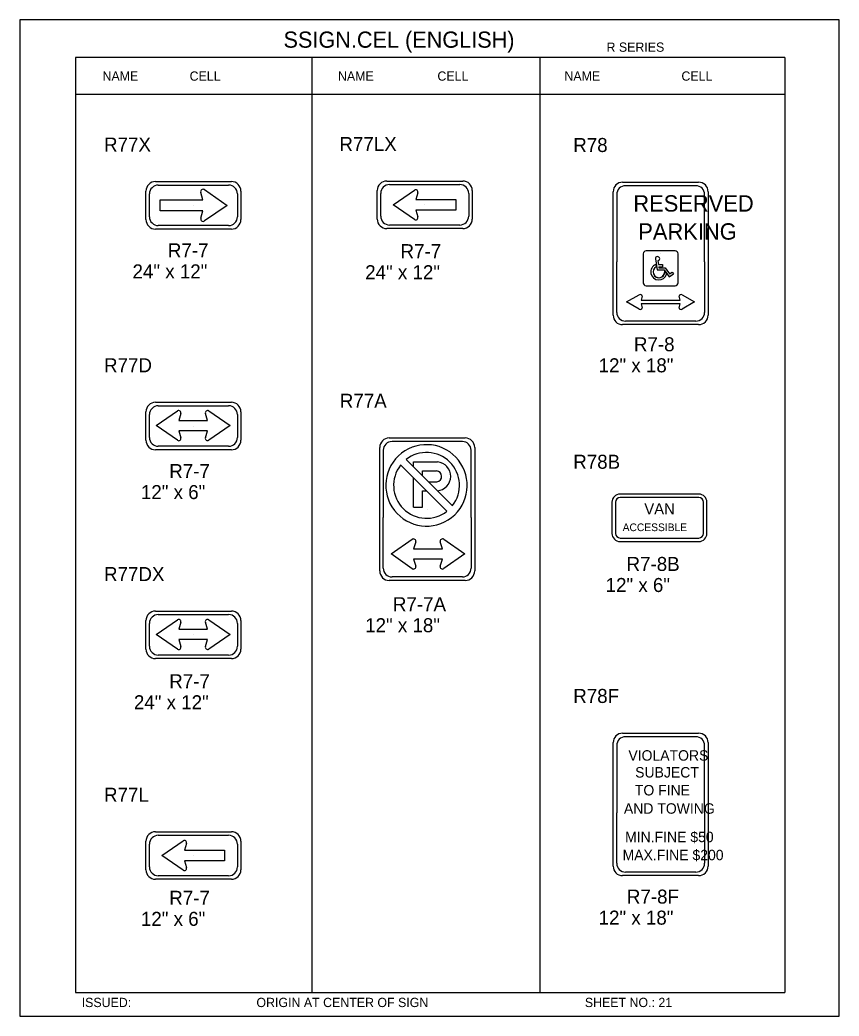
# Model space of a CAD drawing. Extents: x -5299 to 22597, y -19549 to -1808.
# Drawn here: x -3651 to -2950, y -6387 to -5535 of the extents above; entities that cross this region are included whole.
import ezdxf

# ---------------------------------------------------------------- set-up
doc = ezdxf.new("R2010")
doc.units = 0
for name, color, linetype in [('Level 1', 7, 'Continuous'), ('Level 2', 7, 'Continuous'), ('Level 3', 7, 'Continuous'), ('Level 63', 7, 'Continuous')]:
    doc.layers.add(name, color=color, linetype=linetype)

msp = doc.modelspace()

# ---------------------------------------------------------------- linework, layer by layer
at = {"layer": 'Level 1'}
for p, q in [((-2996.59, -5567.18), (-3603.6, -5567.18)), ((-3603.6, -5567.18), (-3603.6, -6367.18)), ((-3401.26, -5567.18), (-3401.26, -6367.18)), ((-3206.14, -5567.18), (-3206.14, -6367.18)), ((-2996.59, -5567.18), (-2996.59, -6367.18)), ((-2996.59, -5598.85), (-3603.6, -5598.85)), ((-3532.72, -5676.35), (-3472.51, -5676.35)), ((-3334.78, -5675.87), (-3274.58, -5675.87)), ((-3540.24, -5703.43), (-3540.24, -5683.86)), ((-3494.43, -5688.87), (-3496.34, -5682.61)), ((-3493.23, -5680.22), (-3473.83, -5693.65)), ((-3465, -5683.86), (-3465, -5703.43)), ((-3342.3, -5702.96), (-3342.3, -5683.39)), ((-3331.67, -5693.18), (-3313.48, -5680.63)), ((-3310.57, -5682.82), (-3312.36, -5688.69)), ((-3267.06, -5683.39), (-3267.06, -5702.96)), ((-3140.4, -5684.37), (-3140.4, -5741.94)), ((-3072.68, -5676.86), (-3132.88, -5676.86)), ((-3065.16, -5741.94), (-3065.16, -5684.37)), ((-3531.09, -5698.43), (-3531.09, -5688.87)), ((-3531.09, -5688.87), (-3494.43, -5688.87)), ((-3502.62, -5693.65), (-3502.62, -5693.65)), ((-3473.83, -5693.65), (-3493.23, -5707.03)), ((-3313.48, -5705.77), (-3331.67, -5693.18)), ((-3312.36, -5688.69), (-3277.99, -5688.69)), ((-3304.68, -5693.18), (-3304.68, -5693.18)), ((-3277.99, -5688.69), (-3277.99, -5697.66)), ((-3494.43, -5698.43), (-3531.09, -5698.43)), ((-3496.34, -5704.69), (-3494.43, -5698.43)), ((-3277.99, -5697.66), (-3312.36, -5697.66)), ((-3312.36, -5697.66), (-3310.57, -5703.53)), ((-3274.58, -5710.48), (-3334.78, -5710.48)), ((-3472.51, -5710.95), (-3532.72, -5710.95)), ((-3117.7, -5735.1), (-3117.7, -5759.95)), ((-3090.37, -5732.62), (-3115.22, -5732.62)), ((-3102.78, -5734.8), (-3102.78, -5734.8)), ((-3087.89, -5759.95), (-3087.89, -5735.1)), ((-3140.4, -5785.22), (-3140.4, -5741.94)), ((-3107.31, -5739.37), (-3105.86, -5748.87)), ((-3106.99, -5744.28), (-3106.69, -5746.2)), ((-3105.14, -5741.21), (-3104.67, -5744.28)), ((-3104.67, -5744.28), (-3101.05, -5744.28)), ((-3101.05, -5744.28), (-3101.05, -5746.14)), ((-3065.16, -5741.94), (-3065.16, -5785.22)), ((-3105.86, -5748.87), (-3099.77, -5748.87)), ((-3104.39, -5746.14), (-3101.05, -5746.14)), ((-3104.39, -5746.14), (-3104.26, -5747.01)), ((-3104.26, -5747.01), (-3098.81, -5747.01)), ((-3099.77, -5748.87), (-3095.55, -5754.78)), ((-3099.31, -5750.11), (-3097.66, -5752.41)), ((-3098.81, -5747.01), (-3095.08, -5752.23)), ((-3095.55, -5754.78), (-3091.81, -5752.28)), ((-3095.08, -5752.23), (-3092.85, -5750.73)), ((-3092.85, -5750.73), (-3091.81, -5752.28)), ((-3131.87, -5776.32), (-3121.28, -5770.19)), ((-3115.22, -5762.43), (-3090.37, -5762.43)), ((-3084.32, -5770.19), (-3073.72, -5776.32)), ((-3121.17, -5782.51), (-3131.87, -5776.32)), ((-3118.68, -5771.25), (-3119.5, -5774.67)), ((-3119.5, -5774.67), (-3102.8, -5774.67)), ((-3102.8, -5777.94), (-3119.44, -5777.94)), ((-3119.44, -5777.94), (-3118.61, -5781.41)), ((-3102.8, -5774.67), (-3086.09, -5774.67)), ((-3086.15, -5777.94), (-3102.8, -5777.94)), ((-3086.98, -5781.41), (-3086.15, -5777.94)), ((-3086.09, -5774.67), (-3086.91, -5771.25)), ((-3073.72, -5776.32), (-3084.42, -5782.51)), ((-3072.68, -5792.74), (-3132.88, -5792.74)), ((-3540.24, -5892.27), (-3540.24, -5872.7)), ((-3534.49, -5882.12), (-3516.3, -5869.58)), ((-3532.72, -5865.19), (-3472.51, -5865.19)), ((-3513.39, -5871.77), (-3515.18, -5877.64)), ((-3490.6, -5877.64), (-3492.39, -5871.77)), ((-3489.48, -5869.53), (-3471.29, -5882.12)), ((-3465, -5872.7), (-3465, -5892.27)), ((-3515.18, -5877.64), (-3509.16, -5877.64)), ((-3509.16, -5877.64), (-3490.6, -5877.64)), ((-3516.3, -5894.72), (-3534.49, -5882.12)), ((-3509.28, -5886.6), (-3515.18, -5886.6)), ((-3515.18, -5886.6), (-3513.39, -5892.48)), ((-3490.6, -5886.6), (-3509.28, -5886.6)), ((-3502.62, -5882.49), (-3502.62, -5882.49)), ((-3492.39, -5892.48), (-3490.6, -5886.6)), ((-3471.29, -5882.12), (-3489.48, -5894.67)), ((-3272.45, -5895.72), (-3332.66, -5895.72)), ((-3472.51, -5899.79), (-3532.72, -5899.79)), ((-3340.17, -5903.24), (-3340.17, -5960.8)), ((-3264.93, -5960.8), (-3264.93, -5903.24)), ((-3320.59, -5911.14), (-3281, -5950.73)), ((-3325.29, -5915.79), (-3285.65, -5955.43)), ((-3301.42, -5930.31), (-3294.29, -5930.31)), ((-3306.71, -5937.93), (-3303.2, -5937.93)), ((-3141.42, -5947.68), (-3141.42, -5974.32)), ((-3070.15, -5943.68), (-3137.42, -5943.68)), ((-3066.15, -5974.32), (-3066.15, -5947.68)), ((-3302.55, -5953.66), (-3302.55, -5953.66)), ((-3340.17, -6004.08), (-3340.17, -5960.8)), ((-3264.93, -5960.8), (-3264.93, -6004.08)), ((-3103.79, -5961), (-3103.79, -5961)), ((-3333.47, -5991.96), (-3315.28, -5979.41)), ((-3312.37, -5981.61), (-3314.16, -5987.48)), ((-3289.58, -5987.48), (-3291.37, -5981.61)), ((-3288.46, -5979.37), (-3270.27, -5991.96)), ((-3137.42, -5978.32), (-3070.15, -5978.32)), ((-3315.28, -6004.55), (-3333.47, -5991.96)), ((-3314.16, -5987.48), (-3308.14, -5987.48)), ((-3308.14, -5987.48), (-3289.58, -5987.48)), ((-3270.27, -5991.96), (-3288.46, -6004.51)), ((-3308.26, -5996.44), (-3314.16, -5996.44)), ((-3314.16, -5996.44), (-3312.37, -6002.31)), ((-3289.58, -5996.44), (-3308.26, -5996.44)), ((-3291.37, -6002.31), (-3289.58, -5996.44)), ((-3272.45, -6011.6), (-3332.65, -6011.6)), ((-3540.24, -6070.94), (-3540.24, -6051.38)), ((-3534.49, -6060.8), (-3516.3, -6048.25)), ((-3532.72, -6043.86), (-3472.51, -6043.86)), ((-3513.39, -6050.44), (-3515.18, -6056.31)), ((-3490.6, -6056.31), (-3492.39, -6050.44)), ((-3489.48, -6048.2), (-3471.29, -6060.8)), ((-3465, -6051.38), (-3465, -6070.94)), ((-3515.18, -6056.31), (-3509.16, -6056.31)), ((-3509.16, -6056.31), (-3490.6, -6056.31)), ((-3516.3, -6073.39), (-3534.49, -6060.8)), ((-3509.28, -6065.28), (-3515.18, -6065.28)), ((-3515.18, -6065.28), (-3513.39, -6071.15)), ((-3490.6, -6065.28), (-3509.28, -6065.28)), ((-3502.62, -6061.16), (-3502.62, -6061.16)), ((-3492.39, -6071.15), (-3490.6, -6065.28)), ((-3471.29, -6060.8), (-3489.48, -6073.34)), ((-3472.51, -6078.46), (-3532.72, -6078.46)), ((-3072.68, -6148.3), (-3132.88, -6148.3)), ((-3140.4, -6155.81), (-3140.4, -6213.37)), ((-3065.16, -6213.37), (-3065.16, -6155.81)), ((-3140.4, -6256.65), (-3140.4, -6213.37)), ((-3102.78, -6206.23), (-3102.78, -6206.23)), ((-3065.16, -6213.37), (-3065.16, -6256.65)), ((-3532.72, -6232.7), (-3472.51, -6232.7)), ((-3529.61, -6250), (-3511.41, -6237.45)), ((-3540.24, -6259.78), (-3540.24, -6240.22)), ((-3508.5, -6239.65), (-3510.29, -6245.52)), ((-3510.29, -6245.52), (-3475.93, -6245.52)), ((-3475.93, -6245.52), (-3475.93, -6254.48)), ((-3465, -6240.22), (-3465, -6259.78)), ((-3511.41, -6262.59), (-3529.61, -6250)), ((-3475.93, -6254.48), (-3510.29, -6254.48)), ((-3510.29, -6254.48), (-3508.5, -6260.35)), ((-3502.62, -6250), (-3502.62, -6250)), ((-3072.68, -6264.17), (-3132.88, -6264.17)), ((-3472.51, -6267.3), (-3532.72, -6267.3)), ((-3603.6, -6367.18), (-2996.59, -6367.18))]:
    msp.add_line(p, q, dxfattribs=at)
for points in [[(-3314.33, -5917.41), (-3314.33, -5913.09), (-3293.64, -5913.19)], [(-3306.71, -5925.02), (-3306.71, -5920.76), (-3294.51, -5920.81)], [(-3314.38, -5951.97), (-3314.33, -5926.8)], [(-3314.38, -5951.97), (-3314.38, -5952.02), (-3306.71, -5951.97), (-3306.71, -5937.93)]]:
    msp.add_lwpolyline(points, dxfattribs=at)
for centre, radius, start, end in [((-3532.72, -5683.86), 7.52, 90, 180), ((-3472.52, -5683.86), 7.52, 0, 90), ((-3334.78, -5683.39), 7.52, 90, 180), ((-3274.58, -5683.39), 7.52, 0, 90), ((-3494.33, -5682), 2.11, 58.03237, 196.37365), ((-3312.45, -5682.27), 1.96, 342.85487, 122.33442), ((-3132.88, -5684.37), 7.52, 90, 180), ((-3072.68, -5684.37), 7.52, 0, 90), ((-3532.72, -5703.43), 7.52, 180, 270), ((-3494.33, -5705.28), 2.09, 162.85487, 302.33442), ((-3472.52, -5703.43), 7.52, 270, 0), ((-3334.78, -5702.96), 7.52, 180, 270), ((-3312.45, -5704.09), 1.98, 238.03237, 16.37365), ((-3274.58, -5702.96), 7.52, 270, 0), ((-3115.22, -5735.1), 2.48, 90, 180), ((-3090.37, -5735.1), 2.48, 0, 90), ((-3104.29, -5750.6), 6.87, 113.13164, 344.68326), ((-3105.45, -5739.37), 1.86, 279.36814, 180), ((-3104.29, -5750.6), 5.01, 118.69491, 0), ((-3104.29, -5750.6), 5.01, 118.69491, 5.58069), ((-3115.22, -5759.95), 2.48, 180, 270), ((-3090.37, -5759.95), 2.48, 270, 0), ((-3132.88, -5785.22), 7.52, 180, 270), ((-3072.68, -5785.22), 7.52, 270, 0), ((-3532.72, -5872.7), 7.52, 90, 180), ((-3515.27, -5871.21), 1.96, 342.85487, 122.33442), ((-3490.51, -5871.21), 1.98, 58.03237, 196.37365), ((-3472.52, -5872.7), 7.52, 0, 90), ((-3532.72, -5892.27), 7.52, 180, 270), ((-3515.27, -5893.04), 1.98, 238.03237, 16.37365), ((-3490.51, -5893.03), 1.96, 162.85487, 302.33442), ((-3472.52, -5892.27), 7.52, 270, 0), ((-3332.66, -5903.24), 7.52, 90, 180), ((-3303.14, -5933.27), 34.84, 308.11415, 307.76212), ((-3272.45, -5903.24), 7.52, 0, 90), ((-3303.12, -5933.26), 28.18, 321.95826, 128.34318), ((-3294.88, -5925.55), 12.42, 274.98032, 84.26909), ((-3303.12, -5933.26), 28.18, 142.1255, 308.3331), ((-3294.96, -5925.58), 4.78, 278.04391, 85.86111), ((-3137.42, -5947.68), 4, 90, 180), ((-3070.15, -5947.68), 4, 0, 90), ((-3137.42, -5974.32), 4, 180, 270), ((-3070.15, -5974.32), 4, 270, 0), ((-3314.25, -5981.05), 1.96, 342.85487, 122.33442), ((-3289.49, -5981.04), 1.98, 58.03237, 196.37365), ((-3332.65, -6004.08), 7.52, 180, 270), ((-3314.25, -6002.88), 1.98, 238.03237, 16.37365), ((-3289.49, -6002.87), 1.96, 162.85487, 302.33442), ((-3272.45, -6004.08), 7.52, 270, 0), ((-3532.72, -6051.37), 7.52, 90, 180), ((-3515.27, -6049.89), 1.96, 342.85487, 122.33442), ((-3490.51, -6049.88), 1.98, 58.03237, 196.37365), ((-3472.52, -6051.37), 7.52, 0, 90), ((-3532.72, -6070.94), 7.52, 180, 270), ((-3515.27, -6071.71), 1.98, 238.03237, 16.37365), ((-3490.51, -6071.7), 1.96, 162.85487, 302.33442), ((-3472.52, -6070.94), 7.52, 270, 0), ((-3132.88, -6155.81), 7.52, 90, 180), ((-3072.68, -6155.81), 7.52, 0, 90), ((-3532.72, -6240.22), 7.52, 90, 180), ((-3510.39, -6239.09), 1.96, 342.85487, 122.33442), ((-3472.52, -6240.22), 7.52, 0, 90), ((-3532.72, -6259.78), 7.52, 180, 270), ((-3510.39, -6260.92), 1.98, 238.03237, 16.37365), ((-3472.52, -6259.78), 7.52, 270, 0), ((-3132.88, -6256.65), 7.52, 180, 270), ((-3072.68, -6256.65), 7.52, 270, 0)]:
    msp.add_arc(centre, radius, start, end, dxfattribs=at)
for centre, start_param, end_param in [((-3120.26, -5771.11), 2.957903, 5.412979), ((-3085.33, -5771.11), 4.011799, 6.466875), ((-3120.18, -5781.61), 0.835066, 3.34671), ((-3085.41, -5781.61), 6.078068, 8.589712)]:
    msp.add_ellipse(centre, major_axis=(-1.58, 0), ratio=0.7337, start_param=start_param, end_param=end_param, dxfattribs=at)
at = {"layer": 'Level 3'}
for p, q in [((-3535.13, -5673.33), (-3470.11, -5673.33)), ((-3337.19, -5672.86), (-3272.17, -5672.86)), ((-3135.29, -5673.84), (-3070.27, -5673.84)), ((-3543.26, -5705.84), (-3543.26, -5681.45)), ((-3461.98, -5681.45), (-3461.98, -5705.84)), ((-3345.32, -5705.37), (-3345.32, -5680.98)), ((-3264.04, -5680.98), (-3264.04, -5705.37)), ((-3143.42, -5741.94), (-3143.42, -5681.97)), ((-3062.14, -5681.97), (-3062.14, -5741.94)), ((-3470.11, -5713.97), (-3535.13, -5713.97)), ((-3272.17, -5713.49), (-3337.19, -5713.49)), ((-3143.42, -5787.63), (-3143.42, -5741.94)), ((-3062.14, -5741.94), (-3062.14, -5787.63)), ((-3070.26, -5795.75), (-3135.3, -5795.75)), ((-3535.13, -5862.17), (-3470.11, -5862.17)), ((-3543.26, -5894.68), (-3543.26, -5870.3)), ((-3461.98, -5870.3), (-3461.98, -5894.68)), ((-3335.06, -5892.7), (-3270.04, -5892.7)), ((-3470.11, -5902.81), (-3535.13, -5902.81)), ((-3343.19, -5960.8), (-3343.19, -5900.83)), ((-3261.92, -5900.83), (-3261.92, -5960.8)), ((-3070.15, -5940.68), (-3137.42, -5940.68)), ((-3144.42, -5947.68), (-3144.42, -5974.32)), ((-3063.15, -5974.32), (-3063.15, -5947.68)), ((-3343.19, -6006.5), (-3343.19, -5960.8)), ((-3261.92, -5960.8), (-3261.92, -6006.5)), ((-3137.42, -5981.32), (-3070.15, -5981.32)), ((-3270.04, -6014.62), (-3335.07, -6014.62)), ((-3535.13, -6040.84), (-3470.11, -6040.84)), ((-3543.26, -6073.35), (-3543.26, -6048.97)), ((-3461.98, -6048.97), (-3461.98, -6073.35)), ((-3470.11, -6081.48), (-3535.13, -6081.48)), ((-3135.29, -6145.28), (-3070.27, -6145.28)), ((-3143.42, -6213.37), (-3143.42, -6153.4)), ((-3062.14, -6153.4), (-3062.14, -6213.37)), ((-3143.42, -6259.07), (-3143.42, -6213.37)), ((-3062.14, -6213.37), (-3062.14, -6259.07)), ((-3535.13, -6229.68), (-3470.11, -6229.68)), ((-3543.26, -6262.19), (-3543.26, -6237.81)), ((-3461.98, -6237.81), (-3461.98, -6262.19)), ((-3470.11, -6270.32), (-3535.13, -6270.32)), ((-3070.26, -6267.19), (-3135.3, -6267.19))]:
    msp.add_line(p, q, dxfattribs=at)
for centre, radius, start, end in [((-3535.13, -5681.45), 8.13, 90, 180), ((-3470.11, -5681.45), 8.13, 0, 90), ((-3337.19, -5680.98), 8.13, 90, 180), ((-3272.17, -5680.98), 8.13, 0, 90), ((-3135.29, -5681.97), 8.13, 90, 180), ((-3070.27, -5681.97), 8.13, 0, 90), ((-3535.13, -5705.84), 8.13, 180, 270), ((-3470.11, -5705.84), 8.13, 270, 0), ((-3337.19, -5705.37), 8.13, 180, 270), ((-3272.17, -5705.37), 8.13, 270, 0), ((-3135.3, -5787.63), 8.12, 180, 270), ((-3070.26, -5787.63), 8.12, 270, 0), ((-3535.13, -5870.3), 8.13, 90, 180), ((-3470.11, -5870.3), 8.13, 0, 90), ((-3535.13, -5894.68), 8.13, 180, 270), ((-3470.11, -5894.68), 8.13, 270, 0), ((-3335.06, -5900.83), 8.13, 90, 180), ((-3270.04, -5900.83), 8.13, 0, 90), ((-3137.42, -5947.68), 7, 90, 180), ((-3070.15, -5947.68), 7, 0, 90), ((-3137.42, -5974.32), 7, 180, 270), ((-3070.15, -5974.32), 7, 270, 0), ((-3335.07, -6006.5), 8.12, 180, 270), ((-3270.04, -6006.5), 8.12, 270, 0), ((-3535.13, -6048.97), 8.13, 90, 180), ((-3470.11, -6048.97), 8.13, 0, 90), ((-3535.13, -6073.35), 8.13, 180, 270), ((-3470.11, -6073.35), 8.13, 270, 0), ((-3135.29, -6153.41), 8.13, 90, 180), ((-3070.27, -6153.41), 8.13, 0, 90), ((-3535.13, -6237.81), 8.13, 90, 180), ((-3470.11, -6237.81), 8.13, 0, 90), ((-3535.13, -6262.19), 8.13, 180, 270), ((-3470.11, -6262.19), 8.13, 270, 0), ((-3135.3, -6259.07), 8.12, 180, 270), ((-3070.26, -6259.07), 8.12, 270, 0)]:
    msp.add_arc(centre, radius, start, end, dxfattribs=at)
at = {"layer": 'Level 63'}
msp.add_lwpolyline([(-3651.11, -6387.37), (-2950.06, -6387.37), (-2950.06, -5534.99), (-3651.11, -5534.99)], close=True, dxfattribs=at)

# ---------------------------------------------------------------- texts
at = {"layer": 'Level 1'}
for s, height, p in [('RESERVED', 14, (-3126.14, -5699)), ('PARKING', 14, (-3121.93, -5723)), ('VAN', 9.484, (-3116.75, -5958.1)), ('ACCESSIBLE', 6.566, (-3135.28, -5972.42)), ('VIOLATORS', 8.944, (-3130.37, -6168.82)), ('SUBJECT', 8.945, (-3124.58, -6183.26)), ('TO FINE', 8.945, (-3124.83, -6198.58)), ('AND TOWING', 8.945, (-3134.21, -6214.23)), ('MIN.FINE $50', 8.9444, (-3133.2, -6238.57)), ('MAX.FINE $200', 8.9444, (-3135.35, -6254.03))]:
    msp.add_text(s, height=height, dxfattribs=at).set_placement(p)
at = {"layer": 'Level 2'}
for s, p in [('R77X', (-3579.14, -5647.63)), ('R77LX', (-3377.71, -5647.16)), ('R78', (-3177.57, -5648.02)), ('R7-7', (-3524.51, -5738.16)), ('R7-7', (-3325.4, -5738.87)), ('24" x 12"', (-3554.74, -5756.16)), ('24" x 12"', (-3355.63, -5756.87)), ('R7-8', (-3125.64, -5818.54)), ('R77D', (-3579.14, -5836.47)), ('12" x 18"', (-3155.87, -5836.54)), ('R77A', (-3377.34, -5866.89)), ('R78B', (-3177.57, -5919.04)), ('R7-7', (-3523.33, -5927.01)), ('12" x 6"', (-3547.57, -5945.01)), ('R7-8B', (-3131.97, -6006.51)), ('R77DX', (-3579.14, -6015.14)), ('12" x 6"', (-3149.87, -6024.51)), ('R7-7A', (-3331.93, -6040.93)), ('12" x 18"', (-3355.65, -6058.93)), ('R7-7', (-3523.33, -6106.85)), ('R78F', (-3177.57, -6119.46)), ('24" x 12"', (-3553.57, -6124.85)), ('R77L', (-3579.14, -6203.98)), ('R7-7', (-3523.33, -6292.17)), ('R7-8F', (-3131.68, -6291.15)), ('12" x 6"', (-3547.57, -6310.17)), ('12" x 18"', (-3155.87, -6309.15))]:
    msp.add_text(s, height=12, dxfattribs=at).set_placement(p)
at = {"layer": 'Level 3'}
for s, height, p in [('SSIGN.CEL (ENGLISH)', 13.8566, (-3425.53, -5558.79)), ('R SERIES', 7.918, (-3149.09, -5562.23)), ('NAME', 7.918, (-3580.41, -5587.01)), ('CELL', 7.918, (-3505.87, -5587.01)), ('NAME', 7.918, (-3378.91, -5587.01)), ('CELL', 7.918, (-3293.8, -5587.01)), ('NAME', 7.918, (-3185.12, -5587.01)), ('CELL', 7.918, (-3084.97, -5587.01)), ('ISSUED:', 7.918, (-3598.24, -6379.67)), ('ORIGIN AT CENTER OF SIGN', 7.9181, (-3448.7, -6379.67)), ('SHEET NO.: 21', 7.918, (-3167.64, -6379.67))]:
    msp.add_text(s, height=height, dxfattribs=at).set_placement(p)

doc.saveas('drawing.dxf')
